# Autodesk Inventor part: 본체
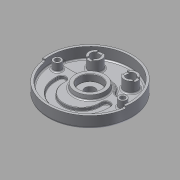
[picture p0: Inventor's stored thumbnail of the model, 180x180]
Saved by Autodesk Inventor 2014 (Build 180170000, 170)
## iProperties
Created: 2015-06
Part Number: 본체
Material: 알루미늄 6061
Document SubType Name: Modeling
Designer: MYHOME
Density: 2.71 g/cm^3
Appearance: 알루미늄 - 평지
Mass: 1070.54 g
Surface Area: 1035.57 cm^2
Volume: 395.033 cm^3
Author: MYHOME
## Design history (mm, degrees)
sketch "스케치1"
  geometry: C1 r 95 at (0, 0); 1 further point
  constraints: 1 centre point, 1 coincident
  dimensions: "d0" = 190 diameter of C1
extrude "돌출1" new body sketch "스케치1" distance "d1" = 32; taper "d2" = 0 deg
sketch "스케치2"
  geometry: C1 r 95 at (0, 0) reference; C2 r 90 at (0, 0)
  constraints: 1 centre point, 1 coincident
  dimensions: "d3" = 180 diameter of C2
extrude "돌출2" cut sketch "스케치2" distance "d4" = 18; taper "d5" = 0 deg
sketch "스케치3"
  geometry: C1 r 90 at (0, 0) reference; C2 r 35 at (0, 0)
  constraints: 1 centre point, 1 coincident
  dimensions: "d6" = 70 diameter of C2
extrude "돌출3" join sketch "스케치3" distance "d7" = 10; taper "d8" = -10 deg
sketch "스케치4"
  geometry: C1 r 95 at (0, 0) reference; C2 r 26 at (0, 0)
  constraints: 1 centre point, 1 coincident
  dimensions: "d9" = 52 diameter of C2
extrude "돌출4" join sketch "스케치4" distance "d10" = 12; taper "d11" = -15 deg
sketch "스케치5"
  geometry: C1 r 33.237 at (0, 0) reference; C2 r 25 at (0, 0)
  constraints: 1 centre point, 1 coincident
  dimensions: "d12" = 50 diameter of C2
extrude "돌출5" cut sketch "스케치5" distance "d13" = 15; taper "d14" = 0 deg
sketch "스케치6"
  geometry: C1 r 22.785 at (0, 0) reference; C2 r 11.5 at (0, 0)
  constraints: 1 centre point, 1 coincident
  dimensions: "d15" = 23 diameter of C2
extrude "돌출6" cut sketch "스케치6" stored distance "d16" = 15; taper "d17" = 0 deg
sketch "스케치7"
  geometry: L1 (-59, -19)-(-41, -19); L2 (41, -19)-(59, -19); L3 (-50, -24)-(-50, -14); L4 (-59, -14)-(-59, -19); L5 (-41, -14)-(-41, -19); L6 (41, -14)-(41, -19); L7 (59, -14)-(59, -19); C1 r 35 at (0, 0) reference; A1 r 41 centre (0, -19) between (-41, -19) and (41, -19); A2 r 59 centre (0, -19) between (-59, -19) and (59, -19); A3 r 9 centre (-50, -14) between (-41, -14) and (-59, -14); A4 r 9 centre (50, -14) between (59, -14) and (41, -14); 1 further point
  constraints: 16 end point, 8 point on circle, 5 tangent, 4 centre point, 2 midpoint, 1 coincident, 1 collinear, 1 horizontal, 1 parallel, 1 perpendicular, 1 vertical alignment
  dimensions: "d18" = 19 distance of A1.centre C1.centre; "d19" = 41 radius of A1; "d20" = 59 radius of A2; "d21" = 18 distance of L2.start L2.end; "d22" = 18 distance of L1.start L1.end; "d23" = 5 distance of point (-50, -19) L3.end; "d25" = 9 radius of A4; "d26" = 5 vertical distance of A1.centre A4.centre
extrude "돌출7" cut sketch "스케치7" distance "d27" = 7; taper "d28" = 0 deg
sketch "스케치9"
  geometry: L1 (-59, -19)-(-59, -14) reference; L2 (-88.566, 16)-(-38.833, 16); L3 (38.833, 16)-(88.566, 16); A1 r 90 centre (0, 0) between (-88.566, 16) and (88.566, 16) reference; A2 r 42 centre (0, 0) between (-38.833, 16) and (38.833, 16)
  constraints: 4 end point, 4 point on circle, 2 collinear, 1 centre point, 1 coincident, 1 perpendicular
  dimensions: "d33" = 84 diameter of A2; "d34" = 16 distance from line of A2.centre L2
extrude "돌출9" cut sketch "스케치9" distance "d35" = 7; taper "d36" = 0 deg
fillet "모깎기2" dims "d37" = 10
sketch "스케치10"
  geometry: C1 r 15 at (-40, 52); C2 r 15 at (40, 52); A1 r 90 centre (0, 0) between (85.114, 29.25) and (-85.114, 29.25) reference
  constraints: 2 centre point, 1 horizontal alignment
  dimensions: "d38" = 30 diameter of C1; "d39" = 30 diameter of C2; "d40" = 80 distance of C2.centre C1.centre; "d41" = 40 horizontal distance of A1.centre C2.centre; "d42" = 52 vertical distance of A1.centre C1.centre
extrude "돌출10" join sketch "스케치10" distance "d43" = 25; taper "d44" = 0 deg
sketch "스케치11"
  geometry: C1 r 15 at (0, 0) reference; C2 r 10 at (0, 0); C3 r 15 at (-80, 0) reference; C4 r 10 at (-80, 0); 1 further point
  constraints: 2 centre point, 2 coincident
  dimensions: "d45" = 20 diameter of C2; "d46" = 20 diameter of C4
extrude "돌출11" cut sketch "스케치11" stored distance "d47" = 25; taper "d48" = 0 deg
sketch "스케치12"
  geometry: L1 (-6, 13.748)-(-6, -13.748); L2 (6, 13.748)-(6, -13.748); L3 (66.252, 6)-(93.748, 6); L4 (66.252, -6)-(93.748, -6); C1 r 10 at (0, 0) reference; C2 r 10 at (80, 0) reference; A1 r 15 centre (0, 0) between (-6, 13.748) and (-6, -13.748) reference; A2 r 15 centre (80, 0) between (66.252, 6) and (93.748, 6) reference; 1 further point
  constraints: 8 end point, 8 point on circle, 2 parallel, 1 perpendicular, 1 vertical
  dimensions: "d49" = 12 distance between parallel lines of L2 L1; "d50" = 12 distance between parallel lines of L4 L3; "d51" = 6 distance from line of L2 C1.centre; "d52" = 6 distance from line of C2.centre L3
extrude "돌출12" cut sketch "스케치12" distance "d53" = 3; taper "d54" = 0 deg
sketch "스케치13"
  geometry: C1 r 26 at (0, 0) reference; C2 r 9 at (-74, 0); C3 r 9 at (74, 0)
  constraints: 2 centre point, 2 horizontal alignment
  dimensions: "d55" = 18 diameter of C2; "d56" = 18 diameter of C3; "d57" = 148 distance of C3.centre C2.centre; "d58" = 74 distance of C2.centre C1.centre
extrude "돌출13" cut sketch "스케치13" distance "d59" = 11; taper "d60" = 0 deg
sketch "스케치14"
  geometry: C1 r 9 at (-74, 0); C2 r 9 at (74, 0); A1 r 90 centre (0, 0) between (-85.114, 29.25) and (85.114, 29.25) reference
  constraints: 2 centre point, 2 horizontal alignment
  dimensions: "d61" = 18 diameter of C1; "d62" = 18 diameter of C2; "d63" = 148 distance of C2.centre C1.centre; "d64" = 74 distance of C1.centre A1.centre
extrude "돌출14" join sketch "스케치14" distance "d65" = 18; taper "d66" = 0 deg
sketch "스케치15"
  geometry: C1 r 9 at (0, 0) reference; C2 r 9 at (148, 0) reference; C3 r 5.5 at (0, 0); C4 r 5.5 at (148, 0); 1 further point
  constraints: 2 centre point, 2 coincident
  dimensions: "d67" = 11 diameter of C3; "d68" = 11 diameter of C4
extrude "돌출15" cut sketch "스케치15" stored distance "d69" = 18; taper "d70" = 0 deg
sketch "스케치16"
  geometry: L1 (0, 0)-(-94.075, -13.221); L2 (0, 0)-(94.075, -13.221); L3 (0, 0)-(-95, 0); L4 (0, 0)-(95, 0); A1 r 90 centre (0, 0) between (-89.124, -12.526) and (89.124, -12.526) reference; A2 r 95 centre (0, 0) between (-94.075, -13.221) and (94.075, -13.221) reference
  constraints: 8 end point, 6 point on circle, 2 point on line, 1 collinear, 1 horizontal
  dimensions: "d71" = 8 deg angle of L1 L3; "d72" = 8 deg angle of L2 L4
extrude "돌출16" cut sketch "스케치16" distance "d73" = 5; taper "d74" = 0 deg
sketch "스케치17"
  geometry: C1 r 95 at (0, 0) reference; C2 r 68 at (0, 0)
  constraints: 1 centre point, 1 coincident, 1 other
  dimensions: "d75" = 136 diameter of C2
feature "엠보싱1" sketch "스케치17" dims "d76" = 0.5, "d77" = 0
fillet "모깎기3" dims "d78" = 0.3
chamfer "모따기1" distance "d79" = 1; stored, may be unused: second distance "d80" = 2, angle "d81" = 45 deg
fillet "모깎기5" dims "d83" = 1
fillet "모깎기6" dims "d84" = 3
fillet "모깎기7" dims "d85" = 3
fillet "모깎기8" dims "d86" = 3
fillet "모깎기9" dims "d87" = 3
chamfer "모따기2" distance "d88" = 1; stored, may be unused: second distance "d89" = 2, angle "d90" = 45 deg
fillet "모깎기10" dims "d91" = 3
fillet "모깎기11" dims "d92" = 5
fillet "모깎기12" dims "d93" = 3
node "솔리드1"
node "투영된 루프1"
node "투영된 루프2"
